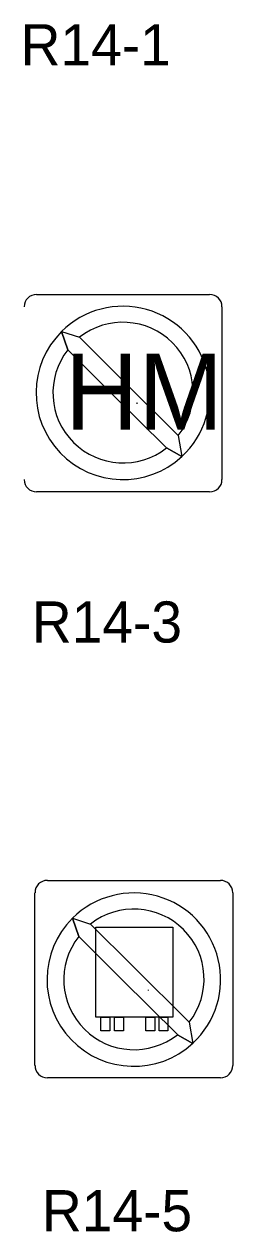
# Model space of a CAD drawing. Extents: x 42133 to 45533, y 41351 to 47951.
# Drawn here: x 42741 to 42778.9, y 41990.2 to 42210.2 of the extents above; entities that cross this region are included whole.
import ezdxf

# ---------------------------------------------------------------- set-up
doc = ezdxf.new("R2010")
doc.units = 0
doc.layers.add('P_TRAF_SIGN_SignDetails', color=7, linetype='Continuous')

msp = doc.modelspace()

# ---------------------------------------------------------------- linework, layer by layer
at = {"layer": 'P_TRAF_SIGN_SignDetails'}
for p, q in [((42743.22, 42160.99), (42774.7, 42160.99)), ((42776.95, 42158.75), (42776.95, 42127.26)), ((42747.78, 42154.24), (42748.91, 42150.91)), ((42747.78, 42154.24), (42751.06, 42153.19)), ((42748.91, 42150.91), (42747.78, 42154.24)), ((42751.06, 42153.19), (42758.86, 42145.39)), ((42756.7, 42143.13), (42748.91, 42150.91)), ((42758.86, 42145.39), (42768.97, 42135.28)), ((42766.84, 42133.03), (42756.7, 42143.14)), ((42761.45, 42141.1), (42761.46, 42141.21)), ((42761.57, 42141.1), (42761.58, 42141.21)), ((42768.99, 42135.29), (42769.65, 42131.45)), ((42768.99, 42135.29), (42769.65, 42131.45)), ((42766.85, 42133.02), (42769.65, 42131.45)), ((42769.65, 42131.45), (42766.85, 42133.02)), ((42774.7, 42125.02), (42743.22, 42125.02)), ((42745.19, 42054.24), (42776.67, 42054.24)), ((42742.94, 42020.51), (42742.94, 42051.99)), ((42778.92, 42051.99), (42778.92, 42020.51)), ((42749.77, 42047.33), (42753.05, 42046.28)), ((42750.9, 42044), (42749.77, 42047.33)), ((42749.77, 42047.33), (42750.9, 42044)), ((42753.05, 42046.28), (42760.85, 42038.48)), ((42758.69, 42036.23), (42750.9, 42044)), ((42760.85, 42038.48), (42770.96, 42028.37)), ((42768.83, 42026.13), (42758.69, 42036.23)), ((42763.56, 42034.19), (42763.57, 42034.3)), ((42770.99, 42028.39), (42771.64, 42024.54)), ((42770.99, 42028.39), (42771.64, 42024.54)), ((42771.64, 42024.54), (42768.84, 42026.11)), ((42768.84, 42026.11), (42771.64, 42024.54)), ((42776.67, 42018.27), (42745.19, 42018.27))]:
    msp.add_line(p, q, dxfattribs=at)
for points in [[(42753.98, 42045.7), (42768.01, 42045.7), (42768.01, 42029.31), (42753.98, 42029.31)], [(42754.91, 42029.31), (42756.54, 42029.32), (42756.54, 42026.83), (42754.91, 42026.83)], [(42757.39, 42029.32), (42759.02, 42029.32), (42759.02, 42026.83), (42757.39, 42026.83)], [(42763.11, 42029.32), (42764.74, 42029.31), (42764.74, 42026.83), (42763.11, 42026.83)], [(42765.5, 42029.31), (42767.12, 42029.31), (42767.12, 42026.83), (42765.5, 42026.83)]]:
    msp.add_lwpolyline(points, close=True, dxfattribs=at)
for centre, radius, start, end in [((42743.22, 42158.75), 2.24, 90, 180), ((42774.71, 42158.75), 2.24, 0, 90), ((42758.93, 42143.05), 15.79, 312.7074, 134.9255), ((42758.93, 42143.05), 15.79, 134.9255, 312.7074), ((42758.94, 42143.16), 12.76, 321.9605, 128.1548), ((42758.96, 42143.05), 12.76, 141.9862, 308.1782), ((42743.22, 42127.26), 2.24, 180, 270), ((42774.71, 42127.26), 2.24, 270, 360), ((42745.19, 42051.99), 2.24, 90, 180), ((42776.67, 42051.99), 2.24, 0, 90), ((42760.92, 42036.15), 15.79, 312.7074, 134.9255), ((42760.94, 42036.25), 12.76, 321.9605, 128.1548), ((42760.92, 42036.15), 15.79, 134.9255, 312.7074), ((42760.95, 42036.14), 12.76, 141.9862, 308.1782), ((42745.19, 42020.51), 2.24, 180, 270), ((42776.67, 42020.51), 2.24, 270, 360)]:
    msp.add_arc(centre, radius, start, end, dxfattribs=at)

# ---------------------------------------------------------------- texts
for s, height, p in [('R14-1', 7.5, (42740.33, 42202.73)), ('HM', 13.845, (42748.37, 42136.36)), ('R14-3', 7.5, (42742.37, 42097.56)), ('R14-5', 7.5, (42744.21, 41990.3))]:
    msp.add_text(s, height=height, dxfattribs=at).set_placement(p)

doc.saveas('drawing.dxf')
